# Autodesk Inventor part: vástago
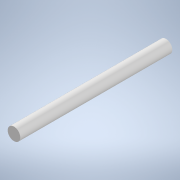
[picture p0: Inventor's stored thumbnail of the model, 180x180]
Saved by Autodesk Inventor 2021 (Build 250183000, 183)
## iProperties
Created: 2021-02
Part Number: vástago
Material: Genérico
Document SubType Name: Modeling
Designer: ATOUZA
Density: 1 g/cm^3
Appearance: Valor por defecto
Author: ATOUZA
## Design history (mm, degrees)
sketch "Boceto1"
  geometry: C1 r 5 at (0, 0); 1 further point
  constraints: 1 centre point, 1 coincident
  dimensions: "d0" = 10 diameter of C1
extrude "Extrusión1" new body sketch "Boceto1" distance "d1" = 120; taper "d2" = 0 deg
node "Sólido1"
